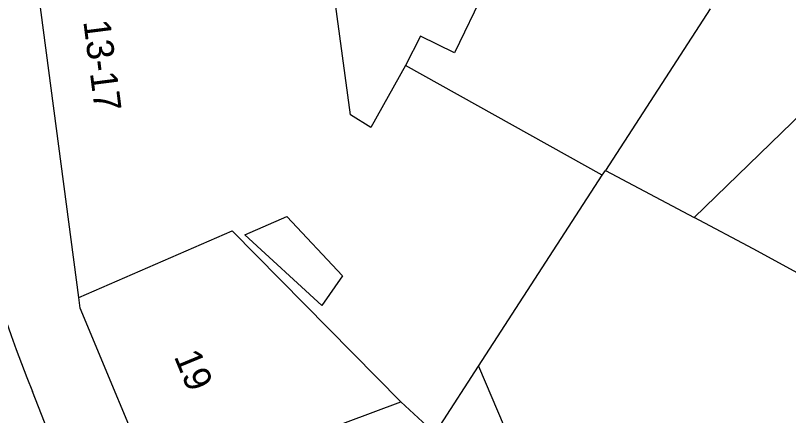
# Model space of a CAD drawing. Extents: x 160664 to 161506, y 382245 to 383288.
# Drawn here: x 161129.57 to 161158.3, y 383156.27 to 383171.15 of the extents above; entities that cross this region are included whole.
import ezdxf

# ---------------------------------------------------------------- set-up
doc = ezdxf.new("R2010")
doc.units = 0
for name, color, linetype in [('IMGEO_Pand', 7, 'Continuous'), ('IMGEO_Pand_nummerreeks', 7, 'Continuous'), ('IMGEO_Parkeervlak_open', 7, 'Continuous'), ('IMGEO_Rijbaan_lokaal_open', 7, 'Continuous'), ('IMGEO_Woonerf_open', 7, 'Continuous')]:
    doc.layers.add(name, color=color, linetype=linetype)

msp = doc.modelspace()

# ---------------------------------------------------------------- linework, layer by layer
at = {"layer": 'IMGEO_Pand'}
for points in [[(161131.927, 383160.664), (161129.783, 383176.901), (161129.809, 383177.129)], [(161141.423, 383171.856), (161142.518, 383174.315), (161146.994, 383172.049), (161145.885, 383169.763), (161144.626, 383170.374), (161144.065, 383169.294)], [(161144.065, 383169.294), (161142.775, 383166.983), (161142.026, 383167.449), (161141.423, 383171.856)], [(161155.385, 383171.391), (161151.498, 383165.39)], [(161151.378, 383165.212), (161144.065, 383169.294)], [(161151.378, 383165.212), (161151.498, 383165.39)], [(161146.783, 383158.104), (161151.378, 383165.212)], [(161139.651, 383163.673), (161141.729, 383161.474), (161140.959, 383160.361), (161138.095, 383162.998), (161139.651, 383163.673)], [(161131.927, 383160.664), (161137.626, 383163.141), (161143.896, 383156.786)], [(161134.843, 383153.401), (161131.982, 383160.267), (161131.927, 383160.664)], [(161143.896, 383156.786), (161145.179, 383155.593), (161145.348, 383155.898), (161146.783, 383158.104)], [(161146.783, 383158.104), (161149.389, 383151.959)], [(161134.843, 383153.401), (161143.896, 383156.786)]]:
    msp.add_lwpolyline(points, dxfattribs=at)
at = {"layer": 'IMGEO_Parkeervlak_open'}
msp.add_lwpolyline([(161151.498, 383165.39), (161154.786, 383163.643)], dxfattribs=at)
at = {"layer": 'IMGEO_Rijbaan_lokaal_open'}
for points in [[(161154.786, 383163.643), (161163.312, 383171.916), (161171.06, 383179.398), (161179.091, 383187.153)], [(161159.601, 383161.046), (161156.987, 383162.473), (161154.786, 383163.643)]]:
    msp.add_lwpolyline(points, dxfattribs=at)
at = {"layer": 'IMGEO_Woonerf_open'}
msp.add_lwpolyline([(161138.12, 383136.927), (161130.21, 383157.169)], dxfattribs=at)
msp.add_arc((161171.449, 383174.177), 44.609, 179.4958, 202.4128, dxfattribs=at)

# ---------------------------------------------------------------- texts
at = {"layer": 'IMGEO_Pand_nummerreeks'}
for s, rotation, p in [('13-17', 277.3222, (161132.093, 383170.928)), ('19', 292.4652, (161135.451, 383158.473))]:
    msp.add_text(s, height=1, rotation=rotation, dxfattribs=at).set_placement(p)

doc.saveas('drawing.dxf')
